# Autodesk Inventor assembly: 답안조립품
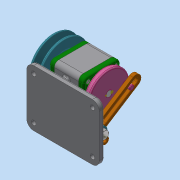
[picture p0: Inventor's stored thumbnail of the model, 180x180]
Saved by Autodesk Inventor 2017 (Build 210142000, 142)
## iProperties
Part Number: 답안조립품
Material: 일반
Document SubType Name: Assembly
Designer: 222
Mass: 1532.4 g
Surface Area: 1486.39 cm^2
Volume: 469.454 cm^3
Density: 3.26422 g/cm^3
Author: 222
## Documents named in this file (19)
- C:\Users\222\Desktop\601106v1039\답안조립품.iam
- C:\Users\222\Desktop\601106v1039\본체.ipt
- C:\Users\222\Desktop\601106v1039\V-벨트풀리.ipt
- C:\Users\222\Desktop\601106v1039\너트 M8.ipt
- C:\Users\222\Desktop\601106v1039\너트 M10x1.ipt
- C:\Users\222\Desktop\601106v1039\돌림판.ipt
- C:\Users\222\Desktop\601106v1039\멈춤나사 M3x5.ipt
- C:\Users\222\Desktop\601106v1039\베어링 6004.ipt
- C:\Users\222\Desktop\601106v1039\볼트 M4.ipt
- C:\Users\222\Desktop\601106v1039\오일 실 17 30 5.ipt
- C:\Users\222\Desktop\601106v1039\와셔 8x15.5.ipt
- C:\Users\222\Desktop\601106v1039\축.ipt
- C:\Users\222\Desktop\601106v1039\커버.ipt
- C:\Users\222\Desktop\601106v1039\크랭크.ipt
- C:\Users\222\Desktop\601106v1039\키 4 x 4 x 8.ipt
- C:\Users\222\Desktop\601106v1039\키 5 x 5 x 12.ipt
- C:\Users\222\Desktop\601106v1039\핀 3 x 8.ipt
- C:\Users\222\Desktop\601106v1039\힌지 축.ipt
- C:\Users\222\Desktop\601106v1039\힌지.ipt
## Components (3 placed, 2 different names)
1. V-벨트풀리:1
2. 핀 3 x 8:1
3. 핀 3 x 8:2
